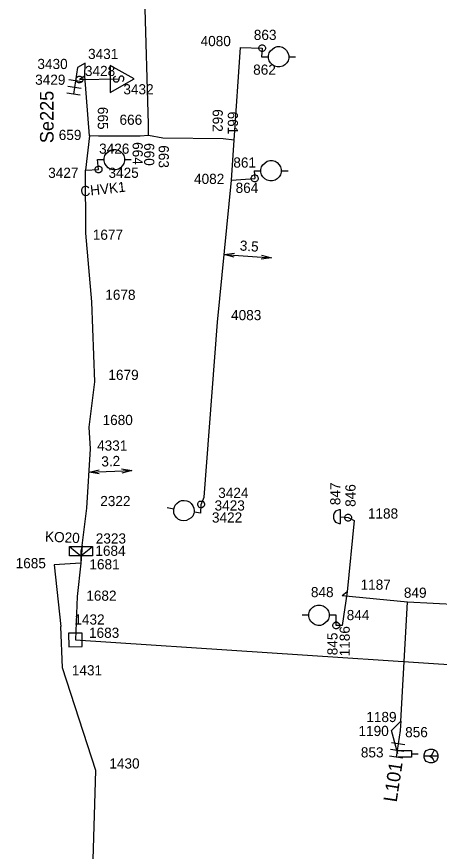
# Model space of a CAD drawing. Extents: x -535557 to -534097, y -1142175 to -1136716.
# Drawn here: x -534488.1 to -534457, y -1141002.2 to -1140940.6 of the extents above; entities that cross this region are included whole.
import ezdxf

# ---------------------------------------------------------------- set-up
doc = ezdxf.new("R2010")
doc.units = 0
doc.layers.add('Default', color=7, linetype='Continuous')
doc.layers.add('SS_SZDC', color=7, linetype='Continuous')

# ---------------------------------------------------------------- blocks, each defined once
blk = doc.blocks.new('POINT_DISPLAY')
at = {"layer": 'Default'}
blk.add_line((0, 0), (0, 0), dxfattribs=at)

msp = doc.modelspace()

# ---------------------------------------------------------------- linework, layer by layer
at = {"layer": 'SS_SZDC'}
for p, q in [((-534478.399, -1140948.52), (-534479, -1140926.969)), ((-534472.09, -1140949.69), (-534471.619, -1140942.85)), ((-534471.619, -1140942.85), (-534470.01, -1140942.899)), ((-534470.26, -1140942.849), (-534470.21, -1140942.749)), ((-534470.26, -1140942.949), (-534470.26, -1140942.849)), ((-534470.21, -1140943.049), (-534470.26, -1140942.949)), ((-534470.21, -1140942.749), (-534470.16, -1140942.699)), ((-534470.16, -1140943.099), (-534470.21, -1140943.049)), ((-534470.16, -1140942.699), (-534470.06, -1140942.649)), ((-534470.06, -1140943.149), (-534470.16, -1140943.099)), ((-534470.06, -1140942.649), (-534469.96, -1140942.649)), ((-534470.01, -1140942.899), (-534470.06, -1140943.549)), ((-534469.96, -1140943.149), (-534470.06, -1140943.149)), ((-534469.96, -1140942.649), (-534469.86, -1140942.699)), ((-534469.86, -1140943.099), (-534469.96, -1140943.149)), ((-534469.86, -1140942.699), (-534469.81, -1140942.749)), ((-534469.81, -1140943.049), (-534469.86, -1140943.099)), ((-534469.81, -1140942.749), (-534469.76, -1140942.849)), ((-534469.76, -1140942.949), (-534469.81, -1140943.049)), ((-534469.76, -1140942.849), (-534469.76, -1140942.949)), ((-534469.511, -1140943.246), (-534469.412, -1140943.095)), ((-534469.412, -1140943.095), (-534469.114, -1140942.843)), ((-534469.114, -1140942.843), (-534468.914, -1140942.792)), ((-534468.914, -1140942.792), (-534468.714, -1140942.791)), ((-534468.714, -1140942.791), (-534468.514, -1140942.839)), ((-534468.514, -1140942.839), (-534468.363, -1140942.938)), ((-534468.363, -1140942.938), (-534468.212, -1140943.087)), ((-534468.212, -1140943.087), (-534468.112, -1140943.237)), ((-534470.06, -1140943.549), (-534469.56, -1140943.546)), ((-534469.56, -1140943.446), (-534469.511, -1140943.246)), ((-534469.56, -1140943.546), (-534469.56, -1140943.446)), ((-534469.559, -1140943.646), (-534469.56, -1140943.546)), ((-534469.508, -1140943.846), (-534469.559, -1140943.646)), ((-534468.112, -1140943.237), (-534468.06, -1140943.436)), ((-534468.059, -1140943.636), (-534468.108, -1140943.837)), ((-534468.06, -1140943.436), (-534468.059, -1140943.636)), ((-534468.06, -1140943.536), (-534467.56, -1140943.533)), ((-534483.63, -1140944.329), (-534483.942, -1140946.305)), ((-534483.079, -1140944), (-534483.63, -1140944.329)), ((-534483.09, -1140944.959), (-534483.079, -1140944)), ((-534481.219, -1140944.17), (-534481.219, -1140946.17)), ((-534479.469, -1140945.17), (-534481.219, -1140944.17)), ((-534469.407, -1140943.995), (-534469.508, -1140943.846)), ((-534469.256, -1140944.144), (-534469.407, -1140943.995)), ((-534469.105, -1140944.243), (-534469.256, -1140944.144)), ((-534468.905, -1140944.292), (-534469.105, -1140944.243)), ((-534468.705, -1140944.291), (-534468.905, -1140944.292)), ((-534468.505, -1140944.239), (-534468.705, -1140944.291)), ((-534468.356, -1140944.138), (-534468.505, -1140944.239)), ((-534468.207, -1140943.987), (-534468.356, -1140944.138)), ((-534468.108, -1140943.837), (-534468.207, -1140943.987)), ((-534483.7, -1140945.061), (-534483.61, -1140944.995)), ((-534483.61, -1140944.995), (-534483.542, -1140944.973)), ((-534483.542, -1140944.973), (-534483.431, -1140944.974)), ((-534483.09, -1140944.959), (-534483.5, -1140945.219)), ((-534483.431, -1140944.974), (-534483.341, -1140945.019)), ((-534483.341, -1140945.019), (-534483.275, -1140945.109)), ((-534482.75, -1140949.36), (-534483.09, -1140944.959)), ((-534480.969, -1140945.07), (-534480.919, -1140945.02)), ((-534480.919, -1140945.02), (-534480.819, -1140944.97)), ((-534480.469, -1140944.97), (-534480.569, -1140945.07)), ((-534480.319, -1140944.97), (-534480.469, -1140944.97)), ((-534480.219, -1140945.07), (-534480.319, -1140944.97)), ((-534483.292, -1140945.395), (-534484.28, -1140945.239)), ((-534483.746, -1140945.262), (-534483.745, -1140945.151)), ((-534483.724, -1140945.33), (-534483.746, -1140945.262)), ((-534483.745, -1140945.151), (-534483.7, -1140945.061)), ((-534483.658, -1140945.42), (-534483.724, -1140945.33)), ((-534483.568, -1140945.465), (-534483.658, -1140945.42)), ((-534483.457, -1140945.466), (-534483.568, -1140945.465)), ((-534483.5, -1140945.219), (-534480.619, -1140945.17)), ((-534483.389, -1140945.444), (-534483.457, -1140945.466)), ((-534483.299, -1140945.378), (-534483.389, -1140945.444)), ((-534483.254, -1140945.288), (-534483.299, -1140945.378)), ((-534483.275, -1140945.109), (-534483.253, -1140945.177)), ((-534483.253, -1140945.177), (-534483.254, -1140945.288)), ((-534481.219, -1140946.17), (-534479.469, -1140945.17)), ((-534480.969, -1140945.32), (-534480.969, -1140945.07)), ((-534480.869, -1140945.42), (-534480.969, -1140945.32)), ((-534480.719, -1140945.42), (-534480.869, -1140945.42)), ((-534480.619, -1140945.32), (-534480.719, -1140945.42)), ((-534480.569, -1140945.07), (-534480.619, -1140945.32)), ((-534480.319, -1140945.37), (-534480.269, -1140945.32)), ((-534480.269, -1140945.32), (-534480.219, -1140945.22)), ((-534480.219, -1140945.22), (-534480.219, -1140945.07)), ((-534483.449, -1140946.383), (-534484.436, -1140946.227)), ((-534483.37, -1140945.889), (-534484.358, -1140945.733)), ((-534478.399, -1140949.35), (-534478.399, -1140948.52)), ((-534482.75, -1140949.36), (-534483.05, -1140951.909)), ((-534482.1, -1140949.389), (-534482.75, -1140949.36)), ((-534478.399, -1140949.35), (-534479.02, -1140949.399)), ((-534477.35, -1140949.54), (-534478.399, -1140949.35)), ((-534479.02, -1140949.399), (-534482.1, -1140949.389)), ((-534472.899, -1140949.6), (-534477.35, -1140949.54)), ((-534472.09, -1140949.69), (-534472.899, -1140949.6)), ((-534472.27, -1140952.639), (-534472.09, -1140949.69)), ((-534481.52, -1140950.67), (-534481.22, -1140950.42)), ((-534481.22, -1140950.42), (-534481.02, -1140950.37)), ((-534481.02, -1140950.37), (-534480.82, -1140950.37)), ((-534480.82, -1140950.37), (-534480.62, -1140950.42)), ((-534480.62, -1140950.42), (-534480.47, -1140950.52)), ((-534480.47, -1140950.52), (-534480.32, -1140950.67)), ((-534482.079, -1140951.85), (-534482.17, -1140951.12)), ((-534482.17, -1140951.12), (-534481.67, -1140951.12)), ((-534481.67, -1140951.02), (-534481.62, -1140950.82)), ((-534481.67, -1140951.12), (-534481.67, -1140951.02)), ((-534481.67, -1140951.22), (-534481.67, -1140951.12)), ((-534481.62, -1140950.82), (-534481.52, -1140950.67)), ((-534480.32, -1140950.67), (-534480.22, -1140950.82)), ((-534480.22, -1140950.82), (-534480.17, -1140951.02)), ((-534480.17, -1140951.02), (-534480.17, -1140951.22)), ((-534480.17, -1140951.12), (-534479.67, -1140951.12)), ((-534469.659, -1140951.25), (-534469.459, -1140951.2)), ((-534469.459, -1140951.2), (-534469.259, -1140951.2)), ((-534469.259, -1140951.2), (-534469.059, -1140951.25)), ((-534482.326, -1140951.892), (-534482.325, -1140951.781)), ((-534482.325, -1140951.781), (-534482.28, -1140951.691)), ((-534482.28, -1140951.691), (-534482.19, -1140951.625)), ((-534482.19, -1140951.625), (-534482.122, -1140951.603)), ((-534482.122, -1140951.603), (-534482.011, -1140951.604)), ((-534482.011, -1140951.604), (-534481.921, -1140951.649)), ((-534481.921, -1140951.649), (-534481.855, -1140951.739)), ((-534481.855, -1140951.739), (-534481.833, -1140951.807)), ((-534481.833, -1140951.807), (-534481.834, -1140951.918)), ((-534481.62, -1140951.42), (-534481.67, -1140951.22)), ((-534481.52, -1140951.57), (-534481.62, -1140951.42)), ((-534481.37, -1140951.72), (-534481.52, -1140951.57)), ((-534481.22, -1140951.82), (-534481.37, -1140951.72)), ((-534481.02, -1140951.87), (-534481.22, -1140951.82)), ((-534480.62, -1140951.82), (-534480.82, -1140951.87)), ((-534480.47, -1140951.72), (-534480.62, -1140951.82)), ((-534480.32, -1140951.57), (-534480.47, -1140951.72)), ((-534480.22, -1140951.42), (-534480.32, -1140951.57)), ((-534480.17, -1140951.22), (-534480.22, -1140951.42)), ((-534470.109, -1140951.85), (-534470.059, -1140951.65)), ((-534470.059, -1140951.65), (-534469.959, -1140951.5)), ((-534469.959, -1140951.5), (-534469.659, -1140951.25)), ((-534469.059, -1140951.25), (-534468.909, -1140951.35)), ((-534468.909, -1140951.35), (-534468.759, -1140951.5)), ((-534468.759, -1140951.5), (-534468.659, -1140951.65)), ((-534468.659, -1140951.65), (-534468.609, -1140951.85)), ((-534483.05, -1140951.909), (-534482.079, -1140951.85)), ((-534483.02, -1140956.549), (-534483.05, -1140951.909)), ((-534482.304, -1140951.96), (-534482.326, -1140951.892)), ((-534482.238, -1140952.05), (-534482.304, -1140951.96)), ((-534482.148, -1140952.095), (-534482.238, -1140952.05)), ((-534482.037, -1140952.096), (-534482.148, -1140952.095)), ((-534481.969, -1140952.074), (-534482.037, -1140952.096)), ((-534481.879, -1140952.008), (-534481.969, -1140952.074)), ((-534481.834, -1140951.918), (-534481.879, -1140952.008)), ((-534480.82, -1140951.87), (-534481.02, -1140951.87)), ((-534470.819, -1140952.46), (-534470.769, -1140952.36)), ((-534470.769, -1140952.36), (-534470.719, -1140952.31)), ((-534470.719, -1140952.31), (-534470.619, -1140952.26)), ((-534470.619, -1140952.26), (-534470.519, -1140952.26)), ((-534470.609, -1140951.95), (-534470.569, -1140952.51)), ((-534470.609, -1140951.95), (-534470.109, -1140951.95)), ((-534470.519, -1140952.26), (-534470.419, -1140952.31)), ((-534470.419, -1140952.31), (-534470.369, -1140952.36)), ((-534470.369, -1140952.36), (-534470.319, -1140952.46)), ((-534470.109, -1140951.95), (-534470.109, -1140951.85)), ((-534470.109, -1140952.05), (-534470.109, -1140951.95)), ((-534470.059, -1140952.25), (-534470.109, -1140952.05)), ((-534469.959, -1140952.4), (-534470.059, -1140952.25)), ((-534469.809, -1140952.55), (-534469.959, -1140952.4)), ((-534468.759, -1140952.4), (-534468.909, -1140952.55)), ((-534468.659, -1140952.25), (-534468.759, -1140952.4)), ((-534468.609, -1140952.05), (-534468.659, -1140952.25)), ((-534468.609, -1140951.85), (-534468.609, -1140952.05)), ((-534468.609, -1140951.95), (-534468.109, -1140951.95)), ((-534473.31, -1140963.12), (-534472.27, -1140952.639)), ((-534472.27, -1140952.639), (-534470.569, -1140952.51)), ((-534470.819, -1140952.56), (-534470.819, -1140952.46)), ((-534470.769, -1140952.66), (-534470.819, -1140952.56)), ((-534470.719, -1140952.71), (-534470.769, -1140952.66)), ((-534470.619, -1140952.76), (-534470.719, -1140952.71)), ((-534470.519, -1140952.76), (-534470.619, -1140952.76)), ((-534470.419, -1140952.71), (-534470.519, -1140952.76)), ((-534470.369, -1140952.66), (-534470.419, -1140952.71)), ((-534470.319, -1140952.56), (-534470.369, -1140952.66)), ((-534470.319, -1140952.46), (-534470.319, -1140952.56)), ((-534469.659, -1140952.65), (-534469.809, -1140952.55)), ((-534469.459, -1140952.7), (-534469.659, -1140952.65)), ((-534469.259, -1140952.7), (-534469.459, -1140952.7)), ((-534469.059, -1140952.65), (-534469.259, -1140952.7)), ((-534468.909, -1140952.55), (-534469.059, -1140952.65)), ((-534482.59, -1140961.62), (-534483.02, -1140956.549)), ((-534472.814, -1140958.128), (-534472.056, -1140958.03)), ((-534472.814, -1140958.128), (-534469.322, -1140958.37)), ((-534472.076, -1140958.329), (-534472.814, -1140958.128)), ((-534469.322, -1140958.37), (-534470.081, -1140958.468)), ((-534470.06, -1140958.169), (-534469.322, -1140958.37)), ((-534482.359, -1140967.53), (-534482.59, -1140961.62)), ((-534474.289, -1140976.02), (-534473.31, -1140963.12)), ((-534482.789, -1140970.86), (-534482.359, -1140967.53)), ((-534482.67, -1140972.469), (-534482.789, -1140970.86)), ((-534482.96, -1140976.84), (-534482.67, -1140972.469)), ((-534480.387, -1140973.948), (-534479.632, -1140974.073)), ((-534482.783, -1140974.178), (-534482.038, -1140974.003)), ((-534482.783, -1140974.178), (-534479.632, -1140974.073)), ((-534482.028, -1140974.303), (-534482.783, -1140974.178)), ((-534479.632, -1140974.073), (-534480.377, -1140974.248)), ((-534476.306, -1140976.486), (-534476.135, -1140976.361)), ((-534476.135, -1140976.361), (-534475.971, -1140976.286)), ((-534475.971, -1140976.286), (-534475.766, -1140976.268)), ((-534475.766, -1140976.268), (-534475.568, -1140976.299)), ((-534475.568, -1140976.299), (-534475.378, -1140976.38)), ((-534475.378, -1140976.38), (-534475.246, -1140976.502)), ((-534474.765, -1140976.491), (-534474.72, -1140976.401)), ((-534474.72, -1140976.401), (-534474.63, -1140976.335)), ((-534474.63, -1140976.335), (-534474.562, -1140976.313)), ((-534474.562, -1140976.313), (-534474.451, -1140976.314)), ((-534474.52, -1140976.559), (-534474.289, -1140976.02)), ((-534474.451, -1140976.314), (-534474.361, -1140976.359)), ((-534474.361, -1140976.359), (-534474.295, -1140976.449)), ((-534474.295, -1140976.449), (-534474.273, -1140976.517)), ((-534483.289, -1140979.6), (-534482.96, -1140976.84)), ((-534476.525, -1140976.907), (-534477.019, -1140976.828)), ((-534476.541, -1140977.005), (-534476.509, -1140976.808)), ((-534476.522, -1140977.211), (-534476.541, -1140977.005)), ((-534476.509, -1140976.808), (-534476.429, -1140976.618)), ((-534476.429, -1140976.618), (-534476.306, -1140976.486)), ((-534475.246, -1140976.502), (-534475.121, -1140976.673)), ((-534475.121, -1140976.673), (-534475.046, -1140976.837)), ((-534475.046, -1140976.837), (-534475.028, -1140977.043)), ((-534475.028, -1140977.043), (-534475.043, -1140977.141)), ((-534474.766, -1140976.602), (-534474.765, -1140976.491)), ((-534474.744, -1140976.67), (-534474.766, -1140976.602)), ((-534474.678, -1140976.76), (-534474.744, -1140976.67)), ((-534474.588, -1140976.805), (-534474.678, -1140976.76)), ((-534474.477, -1140976.806), (-534474.588, -1140976.805)), ((-534474.55, -1140977.219), (-534474.52, -1140976.559)), ((-534474.409, -1140976.784), (-534474.477, -1140976.806)), ((-534474.319, -1140976.718), (-534474.409, -1140976.784)), ((-534474.274, -1140976.628), (-534474.319, -1140976.718)), ((-534474.273, -1140976.517), (-534474.274, -1140976.628)), ((-534464.599, -1140977.069), (-534464.699, -1140977.219)), ((-534464.349, -1140976.969), (-534464.599, -1140977.069)), ((-534464.25, -1140976.969), (-534464.349, -1140976.969)), ((-534464.25, -1140977.969), (-534464.25, -1140976.969)), ((-534476.447, -1140977.375), (-534476.522, -1140977.211)), ((-534476.322, -1140977.546), (-534476.447, -1140977.375)), ((-534476.19, -1140977.668), (-534476.322, -1140977.546)), ((-534476, -1140977.749), (-534476.19, -1140977.668)), ((-534475.262, -1140977.562), (-534475.597, -1140977.762)), ((-534475.14, -1140977.43), (-534475.262, -1140977.562)), ((-534475.059, -1140977.24), (-534475.14, -1140977.43)), ((-534475.043, -1140977.141), (-534475.059, -1140977.24)), ((-534474.55, -1140977.219), (-534475.043, -1140977.141)), ((-534464.699, -1140977.219), (-534464.75, -1140977.369)), ((-534464.75, -1140977.369), (-534464.75, -1140977.569)), ((-534464.75, -1140977.569), (-534464.699, -1140977.719)), ((-534464.25, -1140977.469), (-534463.67, -1140977.54)), ((-534463.92, -1140977.49), (-534463.87, -1140977.39)), ((-534463.92, -1140977.59), (-534463.92, -1140977.49)), ((-534463.87, -1140977.69), (-534463.92, -1140977.59)), ((-534463.87, -1140977.39), (-534463.82, -1140977.34)), ((-534463.82, -1140977.74), (-534463.87, -1140977.69)), ((-534463.82, -1140977.34), (-534463.72, -1140977.29)), ((-534463.72, -1140977.29), (-534463.62, -1140977.29)), ((-534463.67, -1140977.54), (-534463.22, -1140977.76)), ((-534463.62, -1140977.29), (-534463.52, -1140977.34)), ((-534463.52, -1140977.34), (-534463.47, -1140977.39)), ((-534463.47, -1140977.69), (-534463.52, -1140977.74)), ((-534463.47, -1140977.39), (-534463.42, -1140977.49)), ((-534463.42, -1140977.59), (-534463.47, -1140977.69)), ((-534463.42, -1140977.49), (-534463.42, -1140977.59)), ((-534475.803, -1140977.78), (-534476, -1140977.749)), ((-534475.597, -1140977.762), (-534475.803, -1140977.78)), ((-534464.699, -1140977.719), (-534464.599, -1140977.869)), ((-534464.599, -1140977.869), (-534464.349, -1140977.969)), ((-534464.349, -1140977.969), (-534464.25, -1140977.969)), ((-534463.72, -1140977.79), (-534463.82, -1140977.74)), ((-534463.22, -1140977.76), (-534463.76, -1140983.01)), ((-534463.62, -1140977.79), (-534463.72, -1140977.79)), ((-534463.52, -1140977.74), (-534463.62, -1140977.79)), ((-534484.24, -1140979.66), (-534482.54, -1140979.66)), ((-534484.24, -1140980.36), (-534484.24, -1140979.66)), ((-534484.24, -1140979.66), (-534483.39, -1140980.36)), ((-534483.289, -1140979.6), (-534483.39, -1140980.01)), ((-534483.39, -1140980.36), (-534482.54, -1140979.66)), ((-534483.39, -1140980.01), (-534483.38, -1140980.899)), ((-534483.289, -1140979.6), (-534483.38, -1140980.899)), ((-534482.54, -1140979.66), (-534482.54, -1140980.36)), ((-534482.54, -1140980.36), (-534484.24, -1140980.36)), ((-534483.38, -1140980.899), (-534485.369, -1140981.03)), ((-534485.369, -1140981.03), (-534484.869, -1140985.579)), ((-534483.38, -1140980.899), (-534483.67, -1140983.36)), ((-534463.76, -1140983.01), (-534464.109, -1140983.309)), ((-534463.76, -1140983.01), (-534464.109, -1140985.51)), ((-534483.67, -1140983.36), (-534483.789, -1140986.559)), ((-534459.289, -1140983.78), (-534464.109, -1140983.309)), ((-534459.789, -1140992.549), (-534459.289, -1140983.78)), ((-534448.739, -1140984.309), (-534459.289, -1140983.78)), ((-534466.57, -1140984.643), (-534466.521, -1140984.442)), ((-534466.521, -1140984.442), (-534466.422, -1140984.292)), ((-534466.422, -1140984.292), (-534466.273, -1140984.141)), ((-534466.273, -1140984.141), (-534466.124, -1140984.04)), ((-534466.124, -1140984.04), (-534465.924, -1140983.988)), ((-534465.924, -1140983.988), (-534465.724, -1140983.987)), ((-534465.724, -1140983.987), (-534465.524, -1140984.036)), ((-534465.524, -1140984.036), (-534465.373, -1140984.135)), ((-534465.373, -1140984.135), (-534465.222, -1140984.284)), ((-534465.222, -1140984.284), (-534465.121, -1140984.433)), ((-534465.121, -1140984.433), (-534465.07, -1140984.633)), ((-534466.569, -1140984.743), (-534467.069, -1140984.746)), ((-534466.569, -1140984.843), (-534466.57, -1140984.643)), ((-534466.517, -1140985.042), (-534466.569, -1140984.843)), ((-534466.417, -1140985.192), (-534466.517, -1140985.042)), ((-534465.118, -1140985.033), (-534465.217, -1140985.184)), ((-534465.069, -1140984.833), (-534465.118, -1140985.033)), ((-534465.07, -1140984.633), (-534465.069, -1140984.733)), ((-534464.569, -1140984.729), (-534465.069, -1140984.733)), ((-534465.069, -1140984.733), (-534465.069, -1140984.833)), ((-534464.55, -1140985.489), (-534464.569, -1140984.729)), ((-534484.739, -1140988.629), (-534484.869, -1140985.579)), ((-534466.266, -1140985.341), (-534466.417, -1140985.192)), ((-534466.115, -1140985.44), (-534466.266, -1140985.341)), ((-534465.915, -1140985.488), (-534466.115, -1140985.44)), ((-534465.715, -1140985.487), (-534465.915, -1140985.488)), ((-534465.515, -1140985.436), (-534465.715, -1140985.487)), ((-534465.217, -1140985.184), (-534465.515, -1140985.436)), ((-534464.8, -1140985.439), (-534464.75, -1140985.339)), ((-534464.8, -1140985.539), (-534464.8, -1140985.439)), ((-534464.75, -1140985.639), (-534464.8, -1140985.539)), ((-534464.75, -1140985.339), (-534464.7, -1140985.289)), ((-534464.7, -1140985.689), (-534464.75, -1140985.639)), ((-534464.7, -1140985.289), (-534464.6, -1140985.239)), ((-534464.6, -1140985.739), (-534464.7, -1140985.689)), ((-534464.6, -1140985.239), (-534464.5, -1140985.239)), ((-534464.109, -1140985.51), (-534464.55, -1140985.489)), ((-534464.5, -1140985.239), (-534464.4, -1140985.289)), ((-534464.4, -1140985.689), (-534464.5, -1140985.739)), ((-534464.4, -1140985.289), (-534464.35, -1140985.339)), ((-534464.35, -1140985.639), (-534464.4, -1140985.689)), ((-534464.35, -1140985.339), (-534464.3, -1140985.439)), ((-534464.3, -1140985.539), (-534464.35, -1140985.639)), ((-534464.3, -1140985.439), (-534464.3, -1140985.539)), ((-534483.293, -1140986.056), (-534484.293, -1140986.063)), ((-534484.293, -1140986.063), (-534484.286, -1140987.063)), ((-534483.286, -1140987.056), (-534483.293, -1140986.056)), ((-534464.5, -1140985.739), (-534464.6, -1140985.739)), ((-534483.789, -1140986.559), (-534429.6, -1140990.139)), ((-534484.286, -1140987.063), (-534483.286, -1140987.056)), ((-534482.289, -1140996.2), (-534484.739, -1140988.629)), ((-534460.489, -1140993.25), (-534459.789, -1140992.549)), ((-534459.789, -1140992.549), (-534459.84, -1140993.239)), ((-534460, -1140994.969), (-534460.489, -1140993.25)), ((-534459.84, -1140993.239), (-534460.139, -1140995.217)), ((-534459.495, -1140994.303), (-534460.484, -1140994.153)), ((-534459.57, -1140994.798), (-534460.559, -1140994.648)), ((-534460, -1140994.719), (-534459, -1140994.719)), ((-534459, -1140994.719), (-534459, -1140995.219)), ((-534458.06, -1140995.029), (-534458.01, -1140994.879)), ((-534458.01, -1140994.879), (-534457.91, -1140994.729)), ((-534457.91, -1140994.729), (-534457.66, -1140994.629)), ((-534457.66, -1140994.629), (-534457.46, -1140994.629)), ((-534457.51, -1140995.029), (-534457.41, -1140994.879)), ((-534457.46, -1140994.629), (-534457.31, -1140994.679)), ((-534457.41, -1140994.879), (-534457.31, -1140994.679)), ((-534457.31, -1140994.679), (-534457.16, -1140994.779)), ((-534457.16, -1140994.779), (-534457.06, -1140995.029)), ((-534459.645, -1140995.292), (-534460.634, -1140995.142)), ((-534459, -1140995.219), (-534460, -1140995.219)), ((-534459, -1140994.969), (-534458.5, -1140994.969)), ((-534458.06, -1140995.229), (-534458.06, -1140995.029)), ((-534457.06, -1140995.129), (-534458.06, -1140995.129)), ((-534458.01, -1140995.379), (-534458.06, -1140995.229)), ((-534457.91, -1140995.529), (-534458.01, -1140995.379)), ((-534457.66, -1140995.629), (-534457.91, -1140995.529)), ((-534457.66, -1140995.129), (-534457.51, -1140995.029)), ((-534457.66, -1140995.129), (-534457.51, -1140995.229)), ((-534457.51, -1140995.229), (-534457.41, -1140995.379)), ((-534457.41, -1140995.379), (-534457.31, -1140995.579)), ((-534457.16, -1140995.479), (-534457.31, -1140995.579)), ((-534457.06, -1140995.229), (-534457.16, -1140995.479)), ((-534457.06, -1140995.029), (-534457.06, -1140995.229)), ((-534457.46, -1140995.629), (-534457.66, -1140995.629)), ((-534457.31, -1140995.579), (-534457.46, -1140995.629)), ((-534482.63, -1141007.459), (-534482.289, -1140996.2))]:
    msp.add_line(p, q, dxfattribs=at)

# ---------------------------------------------------------------- block references
for p in [(-534471.619, -1140942.85), (-534470.01, -1140942.899), (-534470.01, -1140942.899), (-534470.06, -1140943.549), (-534483.63, -1140944.329), (-534483.079, -1140944), (-534483.09, -1140944.959), (-534483.5, -1140945.219), (-534483.5, -1140945.219), (-534480.619, -1140945.17), (-534478.399, -1140948.52), (-534482.75, -1140949.36), (-534478.399, -1140949.35), (-534482.1, -1140949.389), (-534479.02, -1140949.399), (-534477.35, -1140949.54), (-534472.899, -1140949.6), (-534472.09, -1140949.69), (-534482.17, -1140951.12), (-534483.05, -1140951.909), (-534482.079, -1140951.85), (-534482.079, -1140951.85), (-534470.609, -1140951.95), (-534472.27, -1140952.639), (-534470.569, -1140952.51), (-534470.569, -1140952.51), (-534483.02, -1140956.549), (-534482.59, -1140961.62), (-534473.31, -1140963.12), (-534482.359, -1140967.53), (-534482.789, -1140970.86), (-534482.67, -1140972.469), (-534474.289, -1140976.02), (-534482.96, -1140976.84), (-534474.52, -1140976.559), (-534474.52, -1140976.559), (-534474.55, -1140977.219), (-534464.25, -1140977.469), (-534463.67, -1140977.54), (-534463.67, -1140977.54), (-534463.22, -1140977.76), (-534483.39, -1140980.01), (-534483.289, -1140979.6), (-534485.369, -1140981.03), (-534483.38, -1140980.899), (-534463.76, -1140983.01), (-534483.67, -1140983.36), (-534464.109, -1140983.309), (-534459.289, -1140983.78), (-534464.569, -1140984.729), (-534484.869, -1140985.579), (-534464.55, -1140985.489), (-534464.55, -1140985.489), (-534464.109, -1140985.51), (-534483.789, -1140986.559), (-534484.739, -1140988.629), (-534459.789, -1140992.549), (-534460.489, -1140993.25), (-534459.84, -1140993.239), (-534460, -1140994.969), (-534457.56, -1140995.129), (-534482.289, -1140996.2)]:
    msp.add_blockref('POINT_DISPLAY', p, dxfattribs=at)

# ---------------------------------------------------------------- texts
for s, p in [('863', (-534470.634, -1140942.299)), ('4080', (-534474.558, -1140942.753)), ('3431', (-534482.858, -1140943.704)), ('3430', (-534486.594, -1140944.443)), ('3428', (-534483.09, -1140944.959)), ('862', (-534470.681, -1140944.863)), ('3429', (-534486.76, -1140945.605)), ('3432', (-534480.254, -1140946.312)), ('666', (-534480.539, -1140948.559)), ('659', (-534485.021, -1140949.678)), ('3426', (-534482.044, -1140950.694)), ('861', (-534472.145, -1140951.715)), ('3427', (-534485.798, -1140952.472)), ('3425', (-534481.352, -1140952.472)), ('4082', (-534475.042, -1140952.922)), ('864', (-534471.976, -1140953.581)), ('1677', (-534482.509, -1140957.041)), ('1678', (-534481.59, -1140961.47)), ('4083', (-534472.31, -1140962.97)), ('1679', (-534481.359, -1140967.38)), ('1680', (-534481.789, -1140970.71)), ('4331', (-534482.191, -1140972.596)), ('3424', (-534473.258, -1140976.089)), ('2322', (-534481.96, -1140976.69)), ('3423', (-534473.528, -1140977.015)), ('1188', (-534462.22, -1140977.61)), ('3422', (-534473.721, -1140977.903)), ('2323', (-534482.289, -1140979.45)), ('1684', (-534482.32, -1140980.359)), ('1685', (-534488.199, -1140981.274)), ('1681', (-534482.76, -1140981.357)), ('1187', (-534462.76, -1140982.86)), ('1682', (-534482.991, -1140983.671)), ('848', (-534466.422, -1140983.407)), ('849', (-534459.565, -1140983.452)), ('844', (-534463.783, -1140985.101)), ('1432', (-534483.869, -1140985.429)), ('1683', (-534482.789, -1140986.409)), ('1431', (-534484.056, -1140989.177)), ('1189', (-534462.336, -1140992.623)), ('1190', (-534462.911, -1140993.652)), ('856', (-534459.471, -1140993.74)), ('853', (-534462.738, -1140995.231)), ('1430', (-534481.289, -1140996.05))]:
    msp.add_text(s, height=0.75, dxfattribs=at).set_placement(p)
for s, height, rotation, p in [('Se225', 1, 90, (-534485.402, -1140949.912)), ('665', 0.75, 270, (-534482.142, -1140947.237)), ('662', 0.75, 270, (-534473.672, -1140947.407)), ('661', 0.75, 270, (-534472.553, -1140947.581)), ('664', 0.75, 270, (-534479.574, -1140949.833)), ('660', 0.75, 270, (-534478.724, -1140949.906)), ('663', 0.75, 270, (-534477.653, -1140950.069)), ('CHVK1', 0.75, 6.3, (-534483.38, -1140953.853)), ('3.5', 0.75, 356.02623, (-534471.692, -1140957.83)), ('3.2', 0.75, 1.90101, (-534481.871, -1140973.772)), ('847', 0.75, 90, (-534464.248, -1140976.619)), ('846', 0.75, 90, (-534463.131, -1140976.743)), ('KO20', 0.75, 357.3, (-534486.05, -1140979.301)), ('1186', 0.75, 90, (-534463.556, -1140987.774)), ('845', 0.75, 90, (-534464.461, -1140987.692)), ('L101', 1, 81.37562, (-534460.097, -1140998.571))]:
    msp.add_text(s, height=height, rotation=rotation, dxfattribs=at).set_placement(p)

doc.saveas('drawing.dxf')
